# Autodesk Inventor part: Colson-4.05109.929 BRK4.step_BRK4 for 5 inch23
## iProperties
Created: 2010-10
Part Number: Colson-4.05109.929 BRK4.step_BRK4 for 5 inch23
Document SubType Name: Modeling
Designer: Administrator
Density: 1.06 g/cm^3
Material: ABS Plastic
Mass: 73.2412 g
Surface Area: 251.572 cm^2
Volume: 69.0955 cm^3
Author: Administrator
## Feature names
1. Base1
